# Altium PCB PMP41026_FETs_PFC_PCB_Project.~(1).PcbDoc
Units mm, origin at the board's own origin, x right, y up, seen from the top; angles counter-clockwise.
Board outline 125.73 x 87.63 mm, 2 copper layers (Top Layer, Bottom Layer), stack 1.575 mm thick; 24 components, 0 nets, 16 pads, 0 vias.
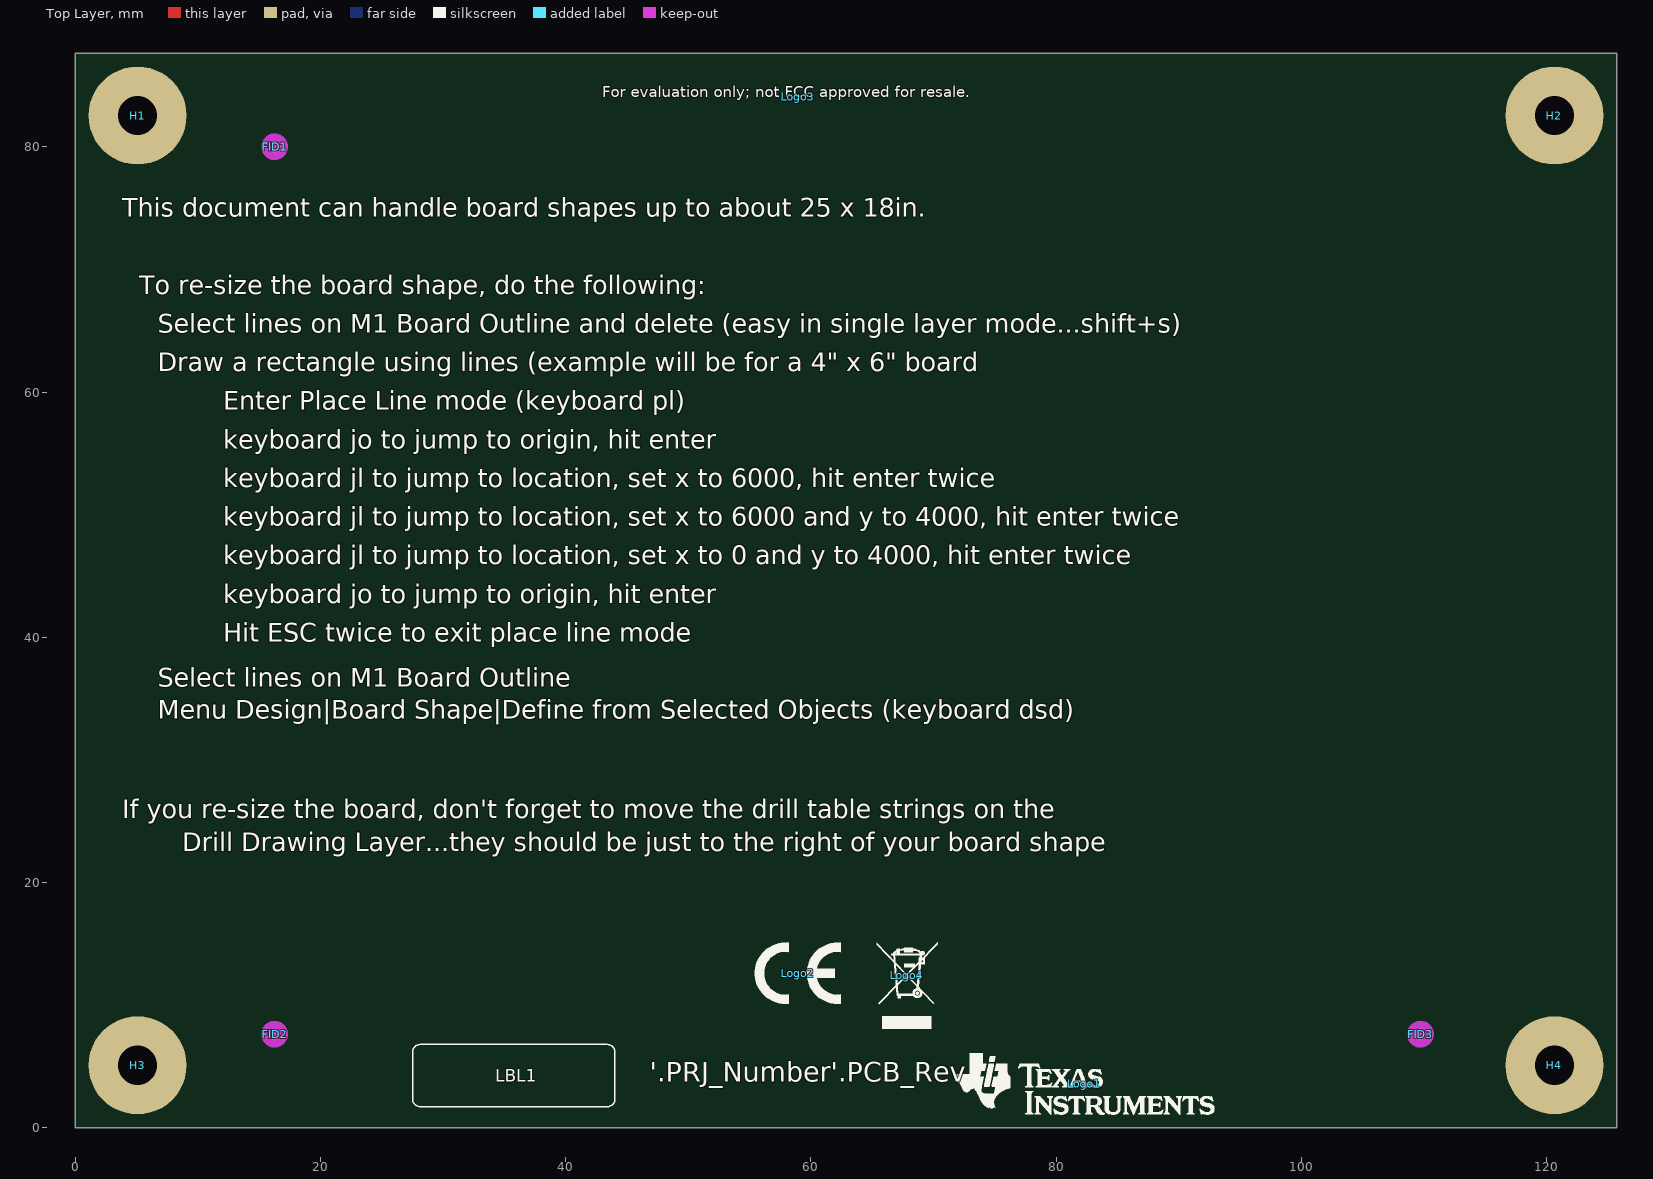
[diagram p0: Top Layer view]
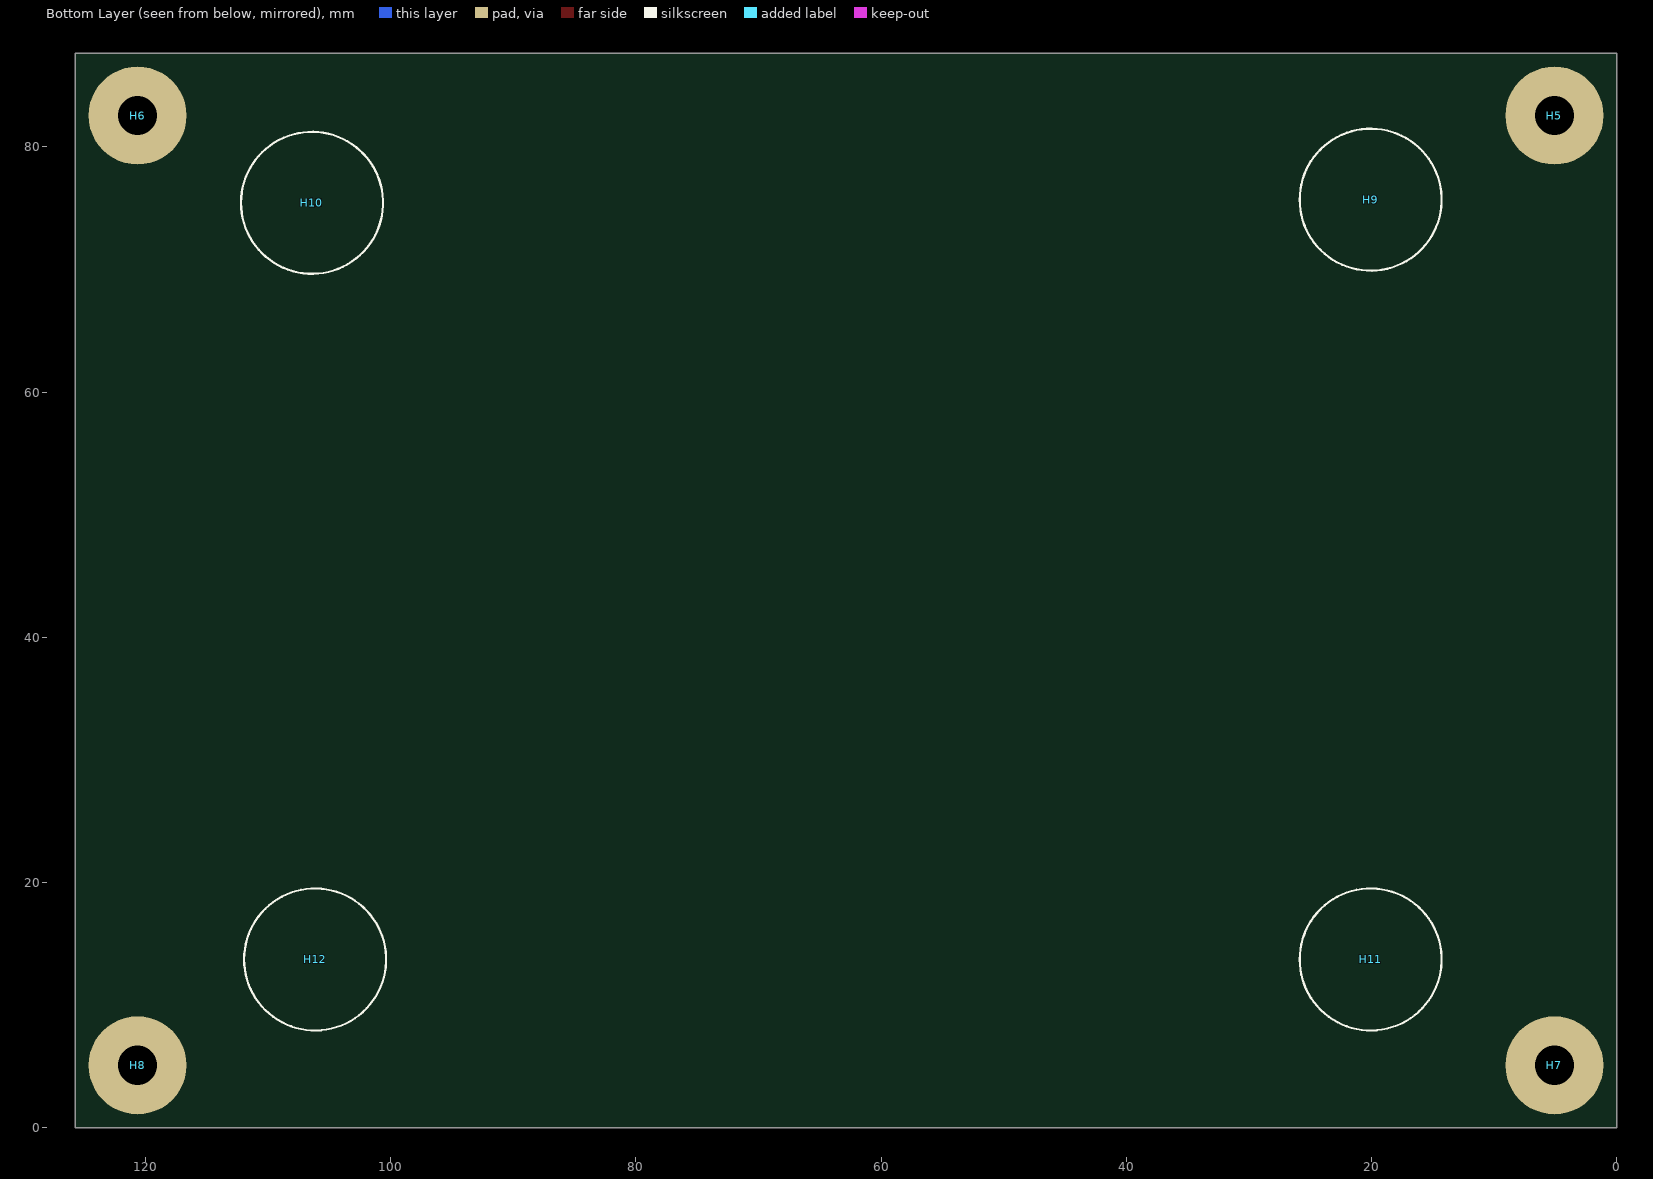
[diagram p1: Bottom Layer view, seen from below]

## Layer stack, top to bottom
Top Solder: solder mask 0.0102, Solder Resist, Dk 3.5
Top Layer: signal copper 0.0356
Dielectric1: core 1.5037, FR-4 High Tg, Dk 4.8
Bottom Layer: signal copper 0.0356
Bottom Solder: solder mask 0.0102, Solder Resist, Dk 3.5

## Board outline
0,0 125.73,0 125.73,87.63 0,87.63

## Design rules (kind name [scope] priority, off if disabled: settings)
AcuteAngle [All] p1: minimum=4.50000000000000E+0001 checktracksonly=FALSE
AssemblyTestPointUsage [All] p1: valid=2
BoardOutlineClearance BoardOutlineClearance_MountingHoles [OnCopper and InComponentClass('Mounting Holes')] p1: gap=1 ignorepadtopadclearanceinfootprint=FALSE
BoardOutlineClearance BoardOutlineClearance_Poly [OnCopper and IsPoly] p2: gap=0.635 ignorepadtopadclearanceinfootprint=FALSE
BoardOutlineClearance [OnCopper and Not InComponentClass('Logo') and not InComponentClass('FiducialMark') and not InRegion(1000,500,4000,800) and not InPoly] p3: gap=1.016 ignorepadtopadclearanceinfootprint=FALSE
Clearance Clearance_Keepouts [((IsTrack Or IsArc) And Not InPoly) And IsFree and IsKeepOut vs ((IsTrack Or IsArc) And Not InPoly) And IsFree and IsKeepOut] p1: gap=0 ignorepadtopadclearanceinfootprint=FALSE
Clearance Clearance_Poly [InPolygon] p2: gap=0.254 ignorepadtopadclearanceinfootprint=TRUE
Clearance Clearance_FiducialMark [IsKeepOut and InComponentClass('FiducialMark') vs IsPad and InComponentClass('FiducialMark')] p3: gap=0 ignorepadtopadclearanceinfootprint=FALSE
Clearance [All] p4: gap=0.2 ignorepadtopadclearanceinfootprint=TRUE
ComponentClearance ComponentClearance_MountingHoles_FiducialMarks [InComponentClass('Mounting Holes') vs InComponentClass('FiducialMark')] p1: gap=1.27 collisioncheckmode=3 verticalgap=0.254 showdistances=FALSE
ComponentClearance ComponentClearance_Shunt [InComponentClass('Header') vs InComponentClass('Shunt')] p2: gap=0 collisioncheckmode=3 verticalgap=0 showdistances=FALSE
ComponentClearance ComponentClearance_Logo [InComponentClass('Logo')] p3: gap=0.762 collisioncheckmode=3 verticalgap=0.254 showdistances=FALSE
ComponentClearance ComponentClearance_ScrewToNut [(HasFootprint('NY PMS 440 0025 PH')) vs (HasFootprint('Keystone_1902C'))] p4: gap=0.127 collisioncheckmode=3 verticalgap=0.254 showdistances=FALSE
ComponentClearance ComponentClearance_MountingHoles [InComponentClass('Mounting Holes')] p5: gap=2.54 collisioncheckmode=3 verticalgap=2540 showdistances=FALSE
ComponentClearance ComponentClearance_SmallPassives [HasFootprint('0201*') or HasFootprint('0402*') or HasFootprint('0508') or HasFootprint('0603*') or HasFootprint('0612') or HasFootprint('0805*') or HasFootprint('0815*') or HasFootprint('0830*') or HasFootprint('1206*') or HasFootprint('1210*') or HasFootprint('1808*') or HasFootprint('1812*') or HasFootprint('1825*') or HasFootprint('2010*') or HasFootprint('2220*') or HasFootprint('2225*') or HasFootprint('2512*') or HasFootprint('2728*') or HasFootprint('3518*') vs HasFootprint('0201*') or HasFootprint('0402*') or HasFootprint('0508') or HasFootprint('0603*') or HasFootprint('0612') or HasFootprint('0805*') or HasFootprint('0815*') or HasFootprint('0830*') or HasFootprint('1206*') or HasFootprint('1210*') or HasFootprint('1808*') or HasFootprint('1812*') or HasFootprint('1825*') or HasFootprint('2010*') or HasFootprint('2220*') or HasFootprint('2225*') or HasFootprint('2512*') or HasFootprint('2728*') or HasFootprint('3518*')] p6: gap=0.38 collisioncheckmode=3 verticalgap=0.254 showdistances=FALSE
ComponentClearance ComponentClearance_THtoSMT [IsThruComponent vs IsSMTComponent] p7: gap=0.762 collisioncheckmode=3 verticalgap=0.762 showdistances=FALSE
ComponentClearance ComponentClearance_THtoTH [IsThruComponent vs IsThruComponent] p8: gap=0.508 collisioncheckmode=3 verticalgap=0.762 showdistances=FALSE
ComponentClearance [All] p9: gap=0.508 collisioncheckmode=3 verticalgap=0.254 showdistances=FALSE
DiffPairsRouting [All] p1: maxlimit=2.54 minlimit=0.254 mostfreqgap=0.254 toplayer_minwidth=0.381 toplayer_maxwidth=0.381 toplayer_prefwidth=0.381 bottomlayer_minwidth=0.381 bottomlayer_maxwidth=0.381 bottomlayer_prefwidth=0.381 maxuncoupledlength=25.4
FabricationTestPointUsage TestPointUsage [All] p1: valid=2 allowmultiple=FALSE
FabricationTestpoint Testpoint [All] p1: side=3 testpointundercomponent=TRUE minsize=1.016 maxsize=2.54 preferedsize=1.524 minholesize=0 maxholesize=1.016 preferedholesize=0.813 testpointgrid=0.025 allowsidetop=TRUE allowsidebottom=TRUE usegrid=TRUE gridtolerance=0
FanoutControl Fanout_LCC [IsLCC] p1: bgadir=Out bgaviamode=Centered fanoutstyle=Auto fanoutdirection=Alternating viagrid=0.025 // Fanout_LCC (Default Rule)
FanoutControl Fanout_BGA [IsBGA] p2: bgadir=Out bgaviamode=Centered fanoutstyle=Auto fanoutdirection=Alternating viagrid=0.025 // Fanout_BGA (Default Rule)
FanoutControl Fanout_Default [All] p4: bgadir=Out bgaviamode=Centered fanoutstyle=Auto fanoutdirection=Alternating viagrid=0.025 // Fanout_Default (Default Rule)
FanoutControl Fanout_Small [(CompPinCount < 5)] p5: bgadir=Out bgaviamode=Centered fanoutstyle=Auto fanoutdirection=OutThenIn viagrid=0.025 // Fanout_Small (Default Rule)
HoleSize [All] p1: absolutevalues=TRUE maxlimit=6.375 minlimit=0.2 maxpercent=80.000 minpercent=20.000
MinimumAnnularRing MinimumAnnularRing_ThermalPadVias [IsVia and InAnyComponent] p1: minimumring=0.15
MinimumAnnularRing [All] p2: minimumring=0.2
MinimumSolderMaskSliver MinimumSolderMaskSliver_Logo [InComponentClass('Logo') vs InComponentClass('Logo')] p1: minsoldermaskwidth=0.018
MinimumSolderMaskSliver [All] p2: minsoldermaskwidth=0.1
PlaneConnect [All] p1: planeconnectstyle=Relief reliefexpansion=0.254 reliefentries=4 reliefconductorwidth=0.254 reliefairgap=0.254
PolygonConnect [All] p1: connectstyle=Relief reliefconductorwidth=0.254 reliefentries=4 polygonreliefangle="90 Angle" airgapwidth=0.254
RoutingVias ThermalPadVias [IsVia and InAnyComponent] p1: holewidth=0.2 width=0.5 viastyle="Through Hole" minholewidth=0.2 minwidth=0.5 maxholewidth=0.33 maxwidth=0.6
RoutingVias [All] p2: holewidth=0.406 width=0.864 viastyle="Through Hole" minholewidth=0.2 minwidth=0.61 maxholewidth=1.016 maxwidth=1.651
SilkToBoardRegionClearance [Not ((IsComment or IsDesignator) And (Hide <> 'False')) and not InRegion(1000,500,4000,800)] p1:
SilkToSilkClearance SilkToSilkClearance_Pb-FreeLogo [(HasFootprint('Pb-Free_Overlay_Medium') OR HasFootprint('Pb-Free_Overlay_Small')) vs (HasFootprint('Pb-Free_Overlay_Medium') OR HasFootprint('Pb-Free_Overlay_Small'))] p1: silktosilkclearance=0
SilkToSilkClearance [All] p2: silktosilkclearance=0.1
SilkToSolderMaskClearance SilkToComponentPadClearance [(IsPad or IsFill or IsRegion) and InAnycomponent] p1: minsilkscreentomaskgap=0.127 clearancetoexposedcopper=TRUE
SilkToSolderMaskClearance "Silk to Solder Mask Opening" [All] p2: minsilkscreentomaskgap=0.1 clearancetoexposedcopper=FALSE
SolderMaskExpansion [All] p1: expansion=0.05 istentingtop=FALSE
UnRoutedNet [All] p1: checkbadconnections=TRUE
Width [All] p1: maxlimit=2.54 minlimit=0.152 preferedwidth=0.254 checkconnectedcopper=TRUE
14 further rules are at their usual default settings.

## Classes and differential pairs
component class "Mounting Holes": H1 H2 H3 H4
component class Logo: Logo1
component class FiducialMark: FID1 FID2 FID3
component class AssemblyNote: ZZ1 ZZ2 ZZ3 ZZ4
component class Label: LBL1

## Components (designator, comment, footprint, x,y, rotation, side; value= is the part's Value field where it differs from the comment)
FID1 "Fiducial" Fiducial10-20 16.256,80.01 r0 top
FID2 "Fiducial" Fiducial10-20 16.256,7.62 r0 top
FID3 "Fiducial" Fiducial10-20 109.728,7.62 r0 top
H1 "NY PMS 440 0025 PH" "NY PMS 440 0025 PH" 5.08,82.55 r0 top locked
H2 "NY PMS 440 0025 PH" "NY PMS 440 0025 PH" 120.65,82.55 r0 top locked
H3 "NY PMS 440 0025 PH" "NY PMS 440 0025 PH" 5.08,5.08 r0 top locked
H4 "NY PMS 440 0025 PH" "NY PMS 440 0025 PH" 120.65,5.08 r0 top locked
H5 "1902C" Keystone_1902C 5.08,82.55 r180 bottom locked
H6 "1902C" Keystone_1902C 120.65,82.55 r180 bottom locked
H7 "1902C" Keystone_1902C 5.08,5.08 r180 bottom locked
H8 "1902C" Keystone_1902C 120.65,5.08 r180 bottom locked
H9 "SJ-5303 (CLEAR)" Bumpon_SJ5003Transparent 20.066,75.692 r180 bottom
H10 "SJ-5303 (CLEAR)" Bumpon_SJ5003Transparent 106.426,75.438 r180 bottom
H11 "SJ-5303 (CLEAR)" Bumpon_SJ5003Transparent 20.066,13.716 r180 bottom
H12 "SJ-5303 (CLEAR)" Bumpon_SJ5003Transparent 106.172,13.716 r180 bottom
LBL1 "THT-14-423-10" Label_650x200 35.763,4.242 r0 top
Logo1 "Texas Instruments" TI_Stacked_Overlay_Small 82.296,3.556 r0 top
Logo2 "CE Mark" CE_Mark_5mm 58.928,12.59 r0 top
Logo3 "FCC disclaimer" FCC_disclaimer 58.928,84.074 r0 top
Logo4 "WEEE logo" WEEE_Minimum 67.818,12.446 r0 top
ZZ1 "This Assembly Note is for PCB labels only" AssemblyNoteLabel 4.699,100.025 r0 top
ZZ2 "These assemblies are ESD sensitive, ESD precautions shall be observed." AssemblyNote 4.699,97.259 r0 top
ZZ3 "These assemblies must be clean and free from flux and all contaminants. Use of no clean flux is not acceptable." AssemblyNote 4.699,95.01 r0 top
ZZ4 "These assemblies must comply with workmanship standards IPC-A-610 Class 2, unless otherwise specified." AssemblyNote 4.699,92.761 r0 top

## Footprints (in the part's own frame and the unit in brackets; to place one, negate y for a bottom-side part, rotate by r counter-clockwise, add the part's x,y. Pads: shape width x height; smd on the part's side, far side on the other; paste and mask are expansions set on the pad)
AssemblyNote [mm] "Assembly Note"
AssemblyNoteLabel [mm] "Assembly Note for PCB Labels"
Bumpon_SJ5003Transparent [mil] "3M Hemispherical Bumpon transparent"
  round 1 on Mech4: 0(0,0)
  silkscreen extent -228,-228 228,228, body extent -219,-219 219,219, height 197
CE_Mark_5mm [mm] "Minimum text height for CE Mark"
  silkscreen extent -3.5,-2.5 3.5,2.5
FCC_disclaimer [mm]
Fiducial10-20 [mm]
  round 1 smd mask+0.5: 1(0,0)
  Top Layer keep-out circle w1.178: c0,0 r0.5
Keystone_1902C [mil] "Hex Standoff, 4-40 threaded, nylon"
  round 1 on Mech4: 0(0,0)
  body extent -145,-126 146,126, height 501
Label_650x200 [mil] "Thermal Transfer Label"
  round 1 on Mech13: 0(0,0)
  silkscreen extent -325,-100 325,100, body extent -325,-100 325,100, height 1
"NY PMS 440 0025 PH" [mm] "4-40 nylon screw and mounting hole"
  round 8 hole 3.2: 1(0,0)
  body extent -3.3,-3.3 3.3,3.3, height 2.69
TI_Stacked_Overlay_Small [mm]
  silkscreen extent -10.63,-2.49 10.63,2.49
WEEE_Minimum [mm] "WEEElie bin"
  silkscreen extent -2.42,-4.38 2.52,2.65

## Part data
FID1 FID2 FID3: library part CMP-0077181-1, "Fiducial mark.  There is nothing to buy or mount.", Manufacturer=N/A
H1 H2 H3 H4: library part CMP-0003617-1, "Machine Screw, Round, #4-40 x 1/4, Nylon, Philips panhead", Manufacturer="B&F Fastener Supply", Supplier Part Number 1=H542-ND
H5 H6 H7 H8: library part CMP-0003610-1, "Standoff, Hex, 0.5\"L #4-40 Nylon", Manufacturer=Keystone, Supplier Part Number 1=36-1902C-ND
H9 H10 H11 H12: library part CMP-0003620-1, "Bumpon, Hemisphere, 0.44 X 0.20, Clear", Manufacturer=3M, Supplier Part Number 1=SJ5303-7-ND
LBL1: library part CMP-0003625-1, "Thermal Transfer Printable Labels, 0.650\" W x 0.200\" H - 10,000 per roll", Manufacturer=Brady, Supplier Part Number 1=97C5133
Logo1: library part CMP-0074838-1, "Texas Instrument Corporate Signature"
Logo2: library part CMP-0074844-1
Logo3: library part CMP-0074847-1, "FCC_disclaimer"
Logo4: library part CMP-0074769-1
ZZ1: library part CMP-0003616-3
ZZ2: library part CMP-0077236-1
ZZ3: library part CMP-0077237-1
ZZ4: library part CMP-0077238-1

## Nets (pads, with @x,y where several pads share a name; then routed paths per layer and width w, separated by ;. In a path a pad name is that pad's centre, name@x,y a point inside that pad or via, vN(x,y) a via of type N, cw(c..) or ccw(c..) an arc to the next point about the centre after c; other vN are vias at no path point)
pads on no net: FID1.1 FID2.1 FID3.1 H1.1 H2.1 H3.1 H4.1 H5.0 H6.0 H7.0 H8.0 H9.0 H10.0 H11.0 H12.0 LBL1.0

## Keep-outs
Keep-Out Layer:
  text ".Layer_Name" at 14.656,-21.806 h1.52

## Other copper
Top Layer:
  text ".Layer_Name" at 14.656,-21.806 h1.52
Bottom Layer:
  text ".Layer_Name" at 14.656,-21.806 h1.52

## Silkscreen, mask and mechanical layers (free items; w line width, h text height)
Top Overlay:
  text "This document can handle board shapes up to about 25 x 18in." at 3.81,74.295 h1.52
  text "To re-size the board shape, do the following:" at 5.207,67.993 h1.52
  text "Select lines on M1 Board Outline and delete (easy in single layer mode...shift+s)" at 6.731,64.842 h1.52
  text "Draw a rectangle using lines (example will be for a 4\" x 6\" board" at 6.731,61.691 h1.52
  text "Enter Place Line mode (keyboard pl)" at 12.065,58.54 h1.52
  text "keyboard jo to jump to origin, hit enter" at 12.065,55.388 h1.52
  text "keyboard jl to jump to location, set x to 6000, hit enter twice" at 12.065,52.237 h1.52
  text "keyboard jl to jump to location, set x to 6000 and y to 4000, hit enter twice" at 12.065,49.086 h1.52
  text "keyboard jl to jump to location, set x to 0 and y to 4000, hit enter twice" at 12.065,45.935 h1.52
  text "keyboard jo to jump to origin, hit enter" at 12.065,42.784 h1.52
  text "Hit ESC twice to exit place line mode" at 12.065,39.633 h1.52
  text "Select lines on M1 Board Outline" at 6.731,35.974 h1.52
  text "Menu Design|Board Shape|Define from Selected Objects (keyboard dsd)" at 6.731,33.331 h1.52
  text "If you re-size the board, don't forget to move the drill table strings on the" at 3.81,25.222 h1.52
  text "Drill Drawing Layer...they should be just to the right of your board shape" at 8.712,22.53 h1.52
  text "'.PRJ_Number'.PCB_Rev" at 46.863,3.195 h2.75
  text ".Layer_Name" at 14.656,-21.806 h1.52
Bottom Overlay:
  text ".Layer_Name" at 14.656,-21.806 h1.52
Top Paste:
  text ".Layer_Name" at 14.656,-21.806 h1.52
Bottom Paste:
  text ".Layer_Name" at 14.656,-21.806 h1.52
Top Solder:
  text ".Layer_Name" at 14.656,-21.806 h1.52
  text ".Layer_Name" at 14.656,-21.806 h1.52
Bottom Solder:
  text ".Layer_Name" at 14.656,-21.806 h1.52
Drill Guide:
  text ".Layer_Name" at 14.656,-21.806 h1.52
M1 Board Outline:
  the board outline again, w0.254
  text ".Layer_Name" at 14.656,-21.806 h1.52
M2 Board Dimensions:
  rectangle: 3.175,-10.16 12.7,-6.985
  rectangle: 0,-6.985 3.175,-3.81
  lines w0.178: 0,-6.985 25.4,-6.985 ; 3.175,-10.16 3.175,-3.81 ; 6.35,-10.16 6.35,-3.81 ; 12.7,-10.16 12.7,-3.81 ; 19.05,-10.16 19.05,-3.81 ; 0,-10.16 0,-3.81 25.4,-3.81 25.4,-10.16 0,-10.16
  text ".Layer_Name" at 14.656,-21.806 h1.52
M3 3D STEP Top:
  text ".Layer_Name" at 14.656,-21.806 h1.52
M4 3D STEP Bottom:
  text ".Layer_Name" at 14.656,-21.806 h1.52
M5 Assembly Top:
  lines w0.254: -7.417,-23.626 160.223,-23.626 ; -7.417,-18.462 160.274,-18.462 ; -7.417,-13.297 -7.417,-28.791 94.31,-28.791 160.274,-28.791 160.274,-13.297 -7.404,-13.297 -7.404,-28.791 32.614,-28.791 ; 55.194,-28.791 55.194,-13.297 ; 87.376,-18.462 87.376,-13.297 ; 108.712,-18.462 108.712,-13.297 ; 124.511,-28.956 124.511,-23.804
  text "COMPONENTS MARKED 'DNP' SHOULD NOT BE POPULATED." at 29.299,-8.09 h1.52
  text "ASSEMBLY VARIANT:" at 29.286,-11.024 h1.52
  text ".VariantName" at 55.601,-11.024 h1.52
  text "PCB VIEWED FROM TOP SIDE" at -5.804,-16.654 h1.52
  text "BOARD #:" at 57.099,-16.654 h1.52
  text ".PRJ_Number" at 70.955,-16.654 h1.52
  text "REV:" at 92.405,-16.654 h1.52
  text ".PCB_Rev" at 99.809,-16.654 h1.52
  text "SVN REV:" at 113.69,-16.654 h1.52
  text ".VersionControl_RevNumber" at 126.543,-16.654 h1.52
  text "PLOT NAME =" at -5.804,-27.034 h1.52
  text ".plot_File_Name" at 14.656,-27.034 h1.52
  text "GENERATED    :" at 57.15,-27.034 h1.52
  text ".Print_Date" at 79.235,-27.034 h1.52
  text ".Print_Time" at 97.752,-27.034 h1.52
  text "TEXAS INSTRUMENTS" at 129.87,-27.034 h1.52
M6 Assembly Bottom:
  lines w0.254: -7.429,-18.474 160.261,-18.474 ; -7.379,-23.639 160.261,-23.639 ; 28.334,-28.969 28.334,-23.817 ; 44.133,-18.474 44.133,-13.31 ; 65.468,-18.474 65.468,-13.31 ; 97.65,-28.804 97.65,-13.31 ; 120.231,-28.804 160.249,-28.804 160.249,-13.31 -7.429,-13.31 -7.429,-28.804 58.534,-28.804 160.261,-28.804 160.261,-13.31
  text "COMPONENTS MARKED 'DNP' SHOULD NOT BE POPULATED." at 154.991,-8.077 h1.52
  text ".VariantName" at 128.473,-11.024 h1.52
  text "ASSEMBLY VARIANT:" at 154.864,-11.024 h1.52
  text ".VersionControl_RevNumber" at 26.302,-16.667 h1.52
  text "SVN REV:" at 39.154,-16.667 h1.52
  text ".PCB_Rev" at 53.035,-16.667 h1.52
  text "REV:" at 60.439,-16.667 h1.52
  text ".PRJ_Number" at 81.89,-16.667 h1.52
  text "BOARD #:" at 95.745,-16.667 h1.52
  text "PCB VIEWED FROM BOTTOM SIDE" at 158.648,-16.667 h1.52
  text "TEXAS INSTRUMENTS" at 22.974,-27.047 h1.52
  text ".Print_Time" at 55.093,-27.047 h1.52
  text ".Print_Date" at 73.609,-27.047 h1.52
  text "GENERATED    :" at 95.694,-27.047 h1.52
  text ".plot_File_Name" at 138.189,-27.047 h1.52
  text "PLOT NAME =" at 158.648,-27.047 h1.52
M9 Title Sheet:
  drawing of 63 lines, arcs and shapes, not listed
  text "1" at 35.293,466.75 h1.78
  text "2" at 136.766,466.75 h1.78
  text "3" at 238.239,466.75 h1.78
  text "4" at 339.865,466.75 h1.78
  text "5" at 441.423,466.75 h1.78
  text "6" at 542.98,466.75 h1.78
  text "7" at 644.623,466.75 h1.78
  text "8" at 746.096,466.75 h1.78
  text "A" at -11.874,405.841 h1.78
  text "A" at 793.305,405.841 h1.78
  text "B" at -11.874,278.841 h1.78
  text "B" at 793.305,278.841 h1.78
  text "C" at -11.874,151.841 h1.78
  text "C" at 793.305,151.841 h1.78
  text "D" at -11.874,24.841 h1.78
  text "D" at 793.305,24.841 h1.78
  text "PROJECT TITLE:" at 714.947,6.823 h1.14
  text ".PRJ_Title" at 716.216,3.436 h1.78
  text "DESIGNED FOR:" at 714.947,-0.823 h1.14
  text ".PRJ_Customer" at 716.216,-4.379 h1.78
  text "FILE NAME:" at 714.947,-8.443 h1.14
  text ".PCB_File_Name_No_Path" at 716.216,-11.491 h1.78
  text "Texas Instruments (TI) and/or its licensors do not warrant the accuracy or completeness of this specification" at 588.721,-15.601 h1.14
  text "ENGINEER:" at 714.947,-15.809 h1.14
  text "LAYOUT BY:" at 753.173,-15.809 h1.14
  text "or any information contained therein. TI and/or its licensors do not warrant that this design will meet" at 587.579,-18.463 h1.14
  text ".PRJ_Engineer" at 716.216,-19.746 h1.78
  text ".PCB_Layout" at 754.456,-19.746 h1.78
  text "the specifications, will be suitable for your application or fit for any particular purpose, or will operate in" at 587.579,-21.325 h1.14
  text ".Layer_Name" at 14.656,-21.806 h1.52
  text "ALTIUM DESIGNER VERSION:" at 753.173,-23.683 h1.14
  text "an implementation. TI and/or its licensors do not warrant that the design is production worthy. You should" at 587.579,-24.187 h1.14
  text "completely validate and test your design implementation to confirm the system functionality for your application." at 588.721,-27.048 h1.14
  text ".print_Scale" at 716.216,-27.069 h1.78
  text ".Application_BuildNumber" at 754.456,-27.069 h1.78
  text "1" at 35.293,-33.503 h1.78
  text "2" at 136.766,-33.503 h1.78
  text "3" at 238.239,-33.503 h1.78
  text "4" at 339.865,-33.503 h1.78
  text "5" at 441.423,-33.503 h1.78
  text "6" at 542.98,-33.503 h1.78
  text "7" at 644.623,-33.503 h1.78
  text "8" at 746.096,-33.503 h1.78
M10 Fab Notes:
  drawing of 189 lines, arcs and shapes, not listed
  text "DESIGN INFORMATION" at 741.376,161.675 h1.52
  text "MIN. TRACK WIDTH:" at 725.004,158.319 h1.52
  text "8" at 752.848,158.32 h1.52
  text "MIL" at 756.779,158.319 h1.52
  text "MIN. CLEARANCE:" at 725.004,155.167 h1.52
  text "7.874" at 748.5,155.167 h1.52
  text "MIL" at 756.779,155.167 h1.52
  text "MIN. VIA PAD SIZE:" at 725.004,152.014 h1.52
  text "24" at 752.087,152.014 h1.52
  text "MIL" at 756.779,152.014 h1.52
  text "0.05mm (2MIL)" at 742.657,148.714 h1.52
  text "MINIMUM ANNULAR RING" at 716.641,148.506 h1.52
  text "EXTERNAL" at 760.64,148.506 h1.52
  text "PER" at 721.721,145.708 h1.52
  text "IPC-D-275 CLASS 2 LEVEL C" at 727.309,145.708 h1.52
  text "MIL, HOLES" at 765.11,143.156 h1.52
  text "+/-" at 755.142,142.938 h1.52
  text "+/-" at 776.834,142.938 h1.52
  text "REGISTRATION TOLERANCES:" at 716.641,142.911 h1.52
  text "METAL" at 747.116,142.911 h1.52
  text "5" at 761.751,142.911 h1.52
  text "3" at 782.909,142.911 h1.52
  text "MIL" at 785.862,142.911 h1.52
  text "HOLE SIZE TOLERANCE (UNLESS OTHERWISE SPECIFIED):" at 716.641,140.414 h1.52
  text "+/-" at 776.834,140.341 h1.52
  text "3" at 782.909,140.314 h1.52
  text "MIL" at 785.862,140.314 h1.52
  text "MATERIAL:" at 714.742,136.818 h1.52
  text "FR-4 High Tg" at 739.798,133.553 h1.52
  text "X" at 736.129,133.35 h1.52
  text "FR-408" at 725.436,133.235 h1.52
  text "OTHER" at 763.231,133.235 h1.52
  text "62 MIL (1.6mm) +/-10%" at 733.566,129.602 h1.52
  text "X" at 730.516,129.54 h1.52
  text "THICKNESS:" at 716.641,129.394 h1.52
  text "OTHER" at 766.203,129.394 h1.52
  text "TOLERANCE:" at 716.641,125.88 h1.52
  text "X" at 738.187,125.88 h1.52
  text "ANSI IPC-6012 TYPE 3 CLASS 2" at 742.708,125.88 h1.52
  text "OTHER +/-" at 742.708,122.218 h1.52
  text "BOW & TWIST:" at 716.641,118.53 h1.52
  text "X" at 738.187,118.53 h1.52
  text "ANSI IPC-6012 TYPE 3 CLASS 2" at 742.708,118.53 h1.52
  text "OTHER +/-" at 742.708,114.804 h1.52
  text "DRILLING:" at 714.742,111.486 h1.52
  text "NC_DRILL FILES" at 759.472,108.815 h1.52
  text "REFERENCE:" at 716.641,108.715 h1.52
  text "X" at 733.335,108.712 h1.52
  text "AS SHOWN" at 737.856,108.715 h1.52
  text "X" at 756.221,108.715 h1.52
  text "OTHER" at 767.041,105.101 h1.52
  text "PTH COPPER THICKNESS:" at 716.633,105.012 h1.52
  text "X" at 745.57,105.012 h1.52
  text "20-30 um" at 748.821,105.012 h1.52
  text "BOARD FINISH:" at 714.742,101.263 h1.52
  text "SILKSCREEN:" at 718.685,98.466 h1.52
  text "X" at 743.013,98.466 h1.52
  text "TOP" at 745.984,98.466 h1.52
  text "X" at 755.967,98.466 h1.52
  text "BOTTOM" at 758.964,98.466 h1.52
  text "SILKSCREEN COLOR:" at 718.685,94.524 h1.52
  text "X" at 742.987,94.524 h1.52
  text "WHITE" at 745.984,94.524 h1.52
  text "OTHER" at 758.964,94.524 h1.52
  text "X" at 746.315,90.88 h1.52
  text "GREEN" at 749.312,90.88 h1.52
  text "OTHER" at 765.009,90.88 h1.52
  text "SOLDER RESIST COLOR:" at 718.685,90.706 h1.52
  text "X" at 746.315,86.962 h1.52
  text "MATTE" at 749.312,86.962 h1.52
  text "SEMI-GLOSS" at 764.997,86.946 h1.52
  text "IMMERSION GOLD (ENIG)" at 741.692,82.574 h1.52
  text "ENEPIG" at 775.665,82.39 h1.52
  text "SURFACE FINISH:" at 714.742,82.365 h1.52
  text "X" at 737.171,82.365 h1.52
  text "IMM. TIN/SILVER OR EQUIV" at 723.113,78.877 h1.52
  text "OTHER" at 759.472,78.777 h1.52
  text "ARRAY/PANEL:" at 714.742,74.831 h1.52
  text "CUT AND TRIM PER M1 BOARD OUTLINE" at 741.692,74.622 h1.52
  text "N.C. ROUTE" at 741.692,71.168 h1.52
  text "X" at 759.167,71.168 h1.52
  text "V. SCORE" at 763.688,71.168 h1.52
  text "CERTIFICATION:" at 714.742,67.888 h1.52
  text "MATERIALS AND WORKMANSHIP FOR ALL PCBS" at 733.157,67.888 h1.52
  text "TO MEET OR EXCEED THE REQUIREMENTS OF:" at 733.157,65.499 h1.52
  text "X" at 723.95,62.232 h1.52
  text "ANSI IPC-A-600F CLASS ->" at 727.201,62.232 h1.52
  text "X" at 769.06,62.232 h1.52
  text "2" at 771.854,62.232 h1.52
  text "1" at 763.853,62.194 h1.52
  text "3" at 780.846,62.194 h1.52
  text "X" at 744.575,58.481 h1.52
  text "RoHS" at 747.826,58.481 h1.52
  text "OTHER" at 764.194,58.481 h1.52
  text "PER ORDER" at 774.279,58.481 h1.52
  text "ALL BOARDS MUST MEET OR EXCEED UL94-V0 REQUIREMENTS." at 715.442,54.574 h1.52
  text "PCB MUST BEAR THE UL94V-0 UL REGISTERED MATERIAL ID NUMBER" at 715.442,51.626 h1.52
  text "ADDITIONAL REQUIREMENTS:" at 714.742,47.322 h1.52
  text "MICROSECTION:" at 716.641,44.601 h1.52
  text "YES" at 739.647,44.601 h1.52
  text "REQUIRED" at 761.529,40.935 h1.52
  text "BARE BOARD ELEC. TEST:" at 716.641,40.863 h1.52
  text "NONE" at 749.807,40.863 h1.52
  text "X" at 758.532,40.863 h1.52
  text "PER ORDER" at 776.566,40.863 h1.52
  text "XX MIL VIAS REQUIRE NON-CONDUCTIVE FILL AND PLANARIZE" at 720.912,35.657 h1.5
  text "XX MIL VIAS REQUIRE CONDUCTIVE FILL AND PLANARIZE" at 721.116,33.016 h1.52
  text "OUTER XX MIL TRACES REQUIRE 50 OHM SINGLE-ENDED IMPEDANCE" at 721.091,28.866 h1.47
  text "LAYER 2 & 3 (INNER LAYERS) XX MIL WIDE, XX MIL SPACE / TRACES REQUIRE 100 OHM DIFFERENTIAL IMPEDANCE" at 720.887,22.879 h1.52
  text ".Layer_Name" at 14.656,-21.806 h1.52
M11 Gerber Information:
  lines w0.254: -7.417,-23.626 160.223,-23.626 ; -7.417,-18.462 160.274,-18.462 ; -7.417,-13.297 -7.417,-28.791 94.31,-28.791 160.274,-28.791 160.274,-13.297 -7.404,-13.297 -7.404,-28.791 32.614,-28.791 ; 55.194,-28.791 55.194,-13.297 ; 87.376,-18.462 87.376,-13.297 ; 108.712,-18.462 108.712,-13.297 ; 124.511,-28.956 124.511,-23.804
  text "ALL ARTWORK VIEWED FROM TOP SIDE" at -5.804,-16.654 h1.52
  text "BOARD #:" at 57.099,-16.654 h1.52
  text ".PRJ_Number" at 70.955,-16.654 h1.52
  text "REV:" at 92.405,-16.654 h1.52
  text ".PCB_Rev" at 99.809,-16.654 h1.52
  text "SVN REV:" at 113.69,-16.654 h1.52
  text ".VersionControl_RevNumber" at 126.543,-16.654 h1.52
  text "LAYER NAME =" at -5.804,-21.806 h1.52
  text "PLOT NAME =" at -5.804,-27.034 h1.52
  text ".plot_File_Name" at 14.656,-27.034 h1.52
  text "GENERATED    :" at 57.15,-27.034 h1.52
  text ".Print_Date" at 79.235,-27.034 h1.52
  text ".Print_Time" at 97.752,-27.034 h1.52
  text "TEXAS INSTRUMENTS" at 129.87,-27.034 h1.52
M12 Stackup:
  drawing of 191 lines, arcs and shapes, not listed
  text "Layer" at 674.469,457.523 h1.52
  text "Name" at 684.88,457.523 h1.52
  text "Material" at 708.496,457.523 h1.52
  text "Thickness" at 730.334,457.523 h1.52
  text "Constant" at 746.84,457.523 h1.52
  text "Board Layer Stack" at 761.314,457.523 h1.52
  text "Top Overlay" at 684.88,454.475 h1.52
  text "Top Solder" at 684.88,451.427 h1.52
  text "Solder Resist" at 708.496,451.427 h1.52
  text "0.40mil" at 730.334,451.427 h1.52
  text "3.5" at 746.84,451.427 h1.52
  text "1" at 674.469,448.379 h1.52
  text "Top Layer" at 684.88,448.379 h1.52
  text "1.40mil" at 730.334,448.379 h1.52
  text "Dielectric1" at 684.88,445.331 h1.52
  text "FR-4 High Tg" at 708.496,445.331 h1.52
  text "59.20mil" at 730.334,445.331 h1.52
  text "4.8" at 746.84,445.331 h1.52
  text "2" at 674.469,442.283 h1.52
  text "Bottom Layer" at 684.88,442.283 h1.52
  text "1.40mil" at 730.334,442.283 h1.52
  text "Bottom Solder" at 684.88,439.235 h1.52
  text "Solder Resist" at 708.496,439.235 h1.52
  text "0.40mil" at 730.334,439.235 h1.52
  text "3.5" at 746.84,439.235 h1.52
  text "Bottom Overlay" at 684.88,436.187 h1.52
  text ".Layer_Name" at 14.656,-21.806 h1.52
M13 Component Bodies Top:
  text ".Layer_Name" at 14.656,-21.806 h1.52
M14 Component Bodies Bottom:
  text ".Layer_Name" at 14.656,-21.806 h1.52
M15 Courtyards Top:
  text ".Layer_Name" at 14.656,-21.806 h1.52
M16 Courtyards Bottom:
  text ".Layer_Name" at 14.656,-21.806 h1.52
Drill Drawing:
  circle w0.254: c144.11,83.426 r0.701
  lines w0.305: 142.138,81.779 224.194,81.779 ; 142.138,84.933 224.194,84.933 ; 150.72,78.625 150.72,88.087 ; 159.153,78.625 159.153,88.087 ; 175.321,78.625 175.321,88.087 ; 181.903,78.625 181.903,88.087 ; 191.432,78.625 191.432,88.087 ; 209.806,78.625 209.806,88.087 ; 142.138,78.625 224.194,78.625 224.194,88.087 142.138,88.087 142.138,78.625
  text "Symbol" at 144.031,85.879 h1.83
  text "Quantity" at 151.666,85.879 h1.83
  text "Finished Hole Size" at 160.099,85.879 h1.83
  text "Plated" at 176.268,85.879 h1.83
  text "Hole Type" at 182.849,85.879 h1.83
  text "Drill Layer Pair" at 192.378,85.879 h1.83
  text "Hole Tolerance" at 210.752,85.879 h1.83
  text "4" at 151.666,82.725 h1.52
  text "125.98mil (3.200mm)" at 160.099,82.725 h1.52
  text "PTH" at 176.268,82.725 h1.52
  text "Round" at 182.849,82.725 h1.52
  text "Top Layer - Bottom Layer" at 192.378,82.725 h1.52
  text "4 Total" at 151.666,79.571 h1.52
  text ".Layer_Name" at 14.656,-21.806 h1.52
M17 Embedded Cavity:
  text ".Layer_Name" at 14.656,-21.806 h1.52
M18 Embedded Assembly:
  text ".Layer_Name" at 14.656,-21.806 h1.52
M19 Embedded Keepout:
  text ".Layer_Name" at 14.91,-21.552 h1.52

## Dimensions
0,-10.16 to 25.4,-10.16 on M2 Board Dimensions
0,0 to 0,87.63 on M2 Board Dimensions
0,0 to 125.73,0 on M2 Board Dimensions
